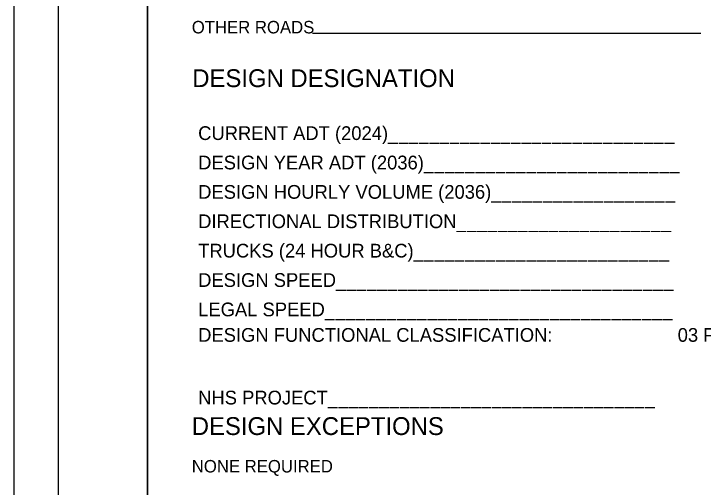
# Model space of a CAD drawing. Extents: x 0 to 34, y 0 to 22.
# Drawn here: x 0 to 7.72, y 5.79 to 11.1 of the extents above; entities that cross this region are included whole.
import ezdxf

# ---------------------------------------------------------------- set-up
doc = ezdxf.new("R2010")
doc.units = 0
for name, color, linetype in [('SH_Border', 7, 'Continuous'), ('SH_Cut_Line', 7, 'Continuous'), ('SH_Data', 7, 'Continuous'), ('SH_Text', 7, 'Continuous')]:
    doc.layers.add(name, color=color, linetype=linetype)

msp = doc.modelspace()

# ---------------------------------------------------------------- linework, layer by layer
at = {"layer": 'SH_Border'}
for points in [[(0.5, 21.5), (1.5, 21.5), (1.5, 0.5), (0.5, 0.5)], [(1.5, 21.5), (33.5, 21.5), (33.5, 0.5), (1.5, 0.5)]]:
    msp.add_lwpolyline(points, close=True, dxfattribs=at)
at = {"layer": 'SH_Cut_Line'}
msp.add_lwpolyline([(0, 0), (34, 0), (34, 22), (0, 22)], close=True, dxfattribs=at)
at = {"layer": 'SH_Data'}
msp.add_line((7.7, 10.8767), (3.3471, 10.8767), dxfattribs=at)

# ---------------------------------------------------------------- texts
msp.add_text('DESIGN DESIGNATION', height=0.2, dxfattribs=at).set_placement((2, 10.2747))
at = {"layer": 'SH_Text'}
for s, height, p in [('OTHER ROADS', 0.14, (1.9944, 10.8767)), ('CURRENT ADT (2024)____________________________', 0.154, (2.0659, 9.6817)), ('DESIGN YEAR ADT (2036)_________________________', 0.154, (2.0659, 9.3523)), ('DESIGN HOURLY VOLUME (2036)__________________', 0.154, (2.0659, 9.0229)), ('DIRECTIONAL DISTRIBUTION_____________________', 0.154, (2.0659, 8.6935)), ('TRUCKS (24 HOUR B&C)_________________________', 0.154, (2.0659, 8.3641)), ('DESIGN SPEED_________________________________', 0.154, (2.0659, 8.0347)), ('LEGAL SPEED__________________________________', 0.154, (2.0659, 7.7052)), ('DESIGN FUNCTIONAL CLASSIFICATION:', 0.154, (2.0659, 7.4195)), ('03 PRINCIPAL ARTERIAL ', 0.154, (7.439, 7.4195)), ('NHS PROJECT________________________________', 0.154, (2.0659, 6.717)), ('DESIGN EXCEPTIONS', 0.2, (1.9944, 6.3744)), ('NONE REQUIRED', 0.14, (1.9944, 5.9544))]:
    msp.add_text(s, height=height, dxfattribs=at).set_placement(p)

doc.saveas('drawing.dxf')
